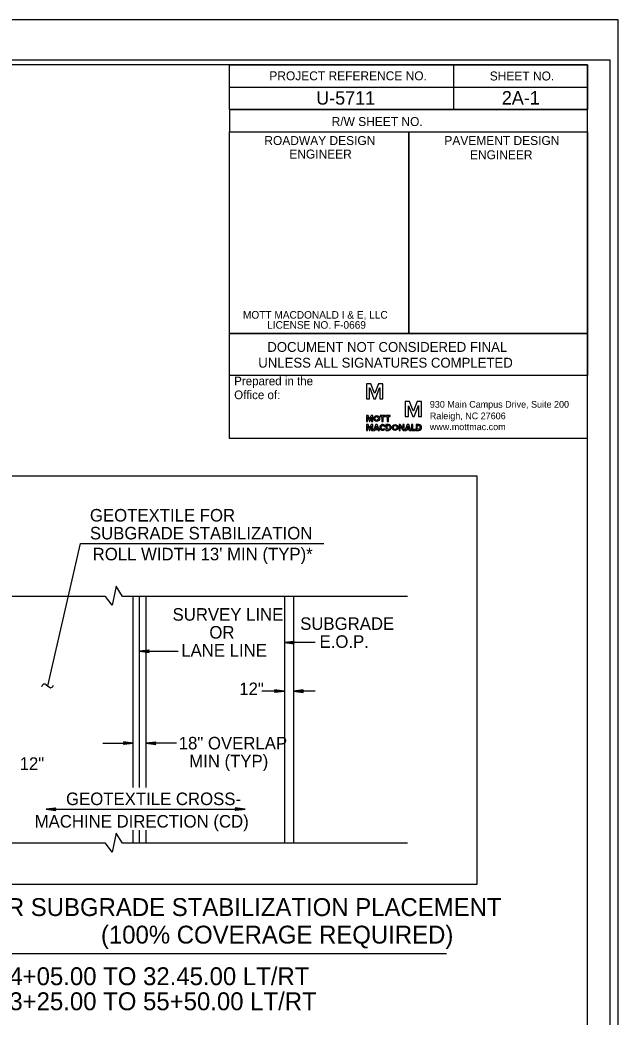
# Model space of a CAD drawing. Extents: x 1901718 to 1902220, y 193828 to 194187.
# Drawn here: x 1902100.8 to 1902134.2, y 194102.3 to 194158 of the extents above; entities that cross this region are included whole.
import ezdxf

# ---------------------------------------------------------------- set-up
doc = ezdxf.new("R2010")
doc.units = 0
for name, color, linetype in [('Old_Level_11', 7, 'Continuous'), ('Old_Level_2', 7, 'Continuous'), ('Old_Level_42', 7, 'Continuous'), ('Old_Level_45', 7, 'Continuous'), ('Prop Dimension Text', 7, 'Continuous'), ('Prop Lane Arrow CELL', 7, 'Continuous'), ('Sheet Border Standard 30in CELL', 7, 'Continuous'), ('Sheet Cutting Line CELL', 7, 'Continuous'), ('Sheet Data Field CELL', 7, 'Continuous'), ('Sheet Plot Border Inside CELL', 7, 'Continuous'), ('Sheet Plot Border Outside CELL', 7, 'Continuous'), ('Sheet Sticker Exception Certification CELL', 7, 'Continuous')]:
    doc.layers.add(name, color=color, linetype=linetype)

msp = doc.modelspace()

# ---------------------------------------------------------------- linework, layer by layer
at = {"layer": 'Old_Level_11'}
msp.add_lwpolyline([(1902088.471, 194132.556), (1902126.343, 194132.556), (1902126.343, 194109.733), (1902088.471, 194109.733)], close=True, dxfattribs=at)
at = {"layer": 'Old_Level_2'}
for p, q in [((1902120.437, 194137.699), (1902120.185, 194137.699)), ((1902120.185, 194137.699), (1902120.185, 194136.849)), ((1902120.642, 194137.174), (1902120.437, 194137.699)), ((1902120.853, 194137.699), (1902120.647, 194137.174)), ((1902121.105, 194137.699), (1902120.853, 194137.699)), ((1902121.105, 194136.849), (1902121.105, 194137.699)), ((1902120.364, 194136.849), (1902120.364, 194137.46)), ((1902120.364, 194137.46), (1902120.366, 194137.46)), ((1902120.366, 194137.46), (1902120.606, 194136.849)), ((1902120.642, 194137.166), (1902120.642, 194137.174)), ((1902120.647, 194137.166), (1902120.642, 194137.166)), ((1902120.647, 194137.174), (1902120.647, 194137.166)), ((1902120.684, 194136.849), (1902120.923, 194137.463)), ((1902120.923, 194137.463), (1902120.925, 194137.463)), ((1902120.925, 194137.463), (1902120.925, 194136.849)), ((1902120.185, 194136.849), (1902120.364, 194136.849)), ((1902120.606, 194136.849), (1902120.684, 194136.849)), ((1902120.925, 194136.849), (1902121.105, 194136.849)), ((1902122.598, 194136.709), (1902122.346, 194136.709)), ((1902122.346, 194136.709), (1902122.346, 194135.859)), ((1902122.803, 194136.184), (1902122.598, 194136.709)), ((1902123.014, 194136.709), (1902122.809, 194136.184)), ((1902123.266, 194136.709), (1902123.014, 194136.709)), ((1902123.266, 194135.859), (1902123.266, 194136.709)), ((1902122.525, 194135.859), (1902122.525, 194136.47)), ((1902122.525, 194136.47), (1902122.528, 194136.47)), ((1902122.528, 194136.47), (1902122.767, 194135.859)), ((1902122.803, 194136.176), (1902122.803, 194136.184)), ((1902122.809, 194136.176), (1902122.803, 194136.176)), ((1902122.809, 194136.184), (1902122.809, 194136.176)), ((1902122.845, 194135.859), (1902123.084, 194136.472)), ((1902123.084, 194136.472), (1902123.087, 194136.472)), ((1902123.087, 194136.472), (1902123.087, 194135.859)), ((1902120.281, 194135.919), (1902120.185, 194135.919)), ((1902120.185, 194135.919), (1902120.185, 194135.594)), ((1902120.185, 194135.594), (1902120.252, 194135.594)), ((1902120.252, 194135.594), (1902120.252, 194135.828)), ((1902120.252, 194135.828), (1902120.255, 194135.828)), ((1902120.252, 194135.828), (1902120.255, 194135.828)), ((1902120.255, 194135.828), (1902120.346, 194135.594)), ((1902120.361, 194135.716), (1902120.281, 194135.919)), ((1902120.346, 194135.594), (1902120.377, 194135.594)), ((1902120.442, 194135.919), (1902120.361, 194135.716)), ((1902120.377, 194135.594), (1902120.468, 194135.828)), ((1902120.538, 194135.919), (1902120.442, 194135.919)), ((1902120.468, 194135.828), (1902120.47, 194135.828)), ((1902120.468, 194135.828), (1902120.47, 194135.828)), ((1902120.468, 194135.828), (1902120.47, 194135.828)), ((1902120.47, 194135.828), (1902120.471, 194135.594)), ((1902120.471, 194135.594), (1902120.538, 194135.594)), ((1902120.538, 194135.594), (1902120.538, 194135.919)), ((1902120.538, 194135.594), (1902120.538, 194135.919)), ((1902122.346, 194135.859), (1902122.525, 194135.859)), ((1902122.767, 194135.859), (1902122.845, 194135.859)), ((1902123.087, 194135.859), (1902123.266, 194135.859)), ((1902120.281, 194135.414), (1902120.185, 194135.414)), ((1902120.185, 194135.414), (1902120.185, 194135.089)), ((1902120.185, 194135.089), (1902120.252, 194135.089)), ((1902120.252, 194135.089), (1902120.252, 194135.323)), ((1902120.252, 194135.323), (1902120.255, 194135.323)), ((1902120.255, 194135.323), (1902120.346, 194135.089)), ((1902120.361, 194135.211), (1902120.281, 194135.414)), ((1902120.346, 194135.089), (1902120.377, 194135.089)), ((1902120.442, 194135.414), (1902120.361, 194135.211)), ((1902120.377, 194135.089), (1902120.468, 194135.323)), ((1902120.538, 194135.414), (1902120.442, 194135.414)), ((1902120.468, 194135.323), (1902120.47, 194135.323)), ((1902120.47, 194135.323), (1902120.471, 194135.089)), ((1902120.471, 194135.089), (1902120.538, 194135.089)), ((1902120.538, 194135.089), (1902120.538, 194135.414)), ((1902121.221, 194135.156), (1902121.164, 194135.184)), ((1902121.221, 194135.156), (1902121.164, 194135.184)), ((1902121.172, 194135.308), (1902121.229, 194135.335)), ((1902121.172, 194135.308), (1902121.229, 194135.334)), ((1902121.422, 194135.414), (1902121.274, 194135.414)), ((1902121.274, 194135.414), (1902121.274, 194135.246)), ((1902121.274, 194135.246), (1902121.274, 194135.089)), ((1902121.274, 194135.089), (1902121.422, 194135.089)), ((1902121.341, 194135.152), (1902121.341, 194135.354)), ((1902121.341, 194135.354), (1902121.422, 194135.354)), ((1902121.422, 194135.152), (1902121.341, 194135.152)), ((1902122.955, 194135.414), (1902122.955, 194135.414)), ((1902123.104, 194135.414), (1902122.955, 194135.414)), ((1902122.955, 194135.414), (1902122.955, 194135.246)), ((1902122.955, 194135.246), (1902122.955, 194135.089)), ((1902122.955, 194135.089), (1902123.104, 194135.089)), ((1902123.023, 194135.152), (1902123.023, 194135.354)), ((1902123.023, 194135.354), (1902123.104, 194135.354)), ((1902123.104, 194135.152), (1902123.023, 194135.152)), ((1902123.104, 194135.352), (1902123.104, 194135.352))]:
    msp.add_line(p, q, dxfattribs=at)
for points in [[(1902120.946, 194135.859), (1902121.04, 194135.859), (1902121.04, 194135.594), (1902121.11, 194135.594), (1902121.11, 194135.859), (1902121.204, 194135.859), (1902121.204, 194135.919), (1902120.946, 194135.919), (1902120.946, 194135.859)], [(1902121.245, 194135.859), (1902121.339, 194135.859), (1902121.339, 194135.594), (1902121.409, 194135.594), (1902121.409, 194135.859), (1902121.502, 194135.859), (1902121.502, 194135.919), (1902121.245, 194135.919), (1902121.245, 194135.859)], [(1902120.577, 194135.089), (1902120.655, 194135.089), (1902120.676, 194135.144), (1902120.816, 194135.144), (1902120.837, 194135.089), (1902120.912, 194135.089), (1902120.788, 194135.414), (1902120.702, 194135.414), (1902120.577, 194135.089)], [(1902120.694, 194135.204), (1902120.746, 194135.344), (1902120.798, 194135.204), (1902120.694, 194135.204)], [(1902122.069, 194135.3), (1902122.072, 194135.3), (1902122.228, 194135.089), (1902122.293, 194135.089), (1902122.293, 194135.414), (1902122.225, 194135.414), (1902122.225, 194135.209), (1902122.072, 194135.414), (1902122.004, 194135.414), (1902122.004, 194135.089), (1902122.069, 194135.089), (1902122.069, 194135.3)], [(1902122.334, 194135.089), (1902122.412, 194135.089), (1902122.433, 194135.144), (1902122.573, 194135.144), (1902122.594, 194135.089), (1902122.67, 194135.089), (1902122.545, 194135.414), (1902122.459, 194135.414), (1902122.334, 194135.089)], [(1902122.451, 194135.204), (1902122.503, 194135.344), (1902122.555, 194135.204), (1902122.451, 194135.204)], [(1902122.917, 194135.089), (1902122.917, 194135.147), (1902122.776, 194135.147), (1902122.776, 194135.414), (1902122.709, 194135.414), (1902122.709, 194135.089), (1902122.917, 194135.089)], [(1902122.917, 194135.089), (1902122.917, 194135.147), (1902122.776, 194135.147), (1902122.776, 194135.414), (1902122.709, 194135.414), (1902122.709, 194135.089), (1902122.917, 194135.09), (1902122.917, 194135.147)]]:
    msp.add_lwpolyline(points, dxfattribs=at)
msp.add_arc((1902123.104, 194135.252), 0.162, 270, 90, dxfattribs=at)
for centre, major_axis, ratio in [((1902120.759, 194135.756), (0, 0.162), 0.993118), ((1902120.759, 194135.756), (0, 0.106), 0.916103), ((1902121.786, 194135.252), (0, 0.162), 0.993118), ((1902121.786, 194135.252), (0, 0.106), 0.916103)]:
    msp.add_ellipse(centre, major_axis=major_axis, ratio=ratio, dxfattribs=at)
for centre, major_axis, ratio, start_param, end_param in [((1902121.09, 194135.252), (0, 0.162), 0.993118, 5.246647, 10.366427), ((1902121.09, 194135.252), (0, 0.162), 0.993118, 5.246647, 10.366427), ((1902121.09, 194135.252), (0, 0.106), 0.916103, 5.276876, 9.424778), ((1902121.09, 194135.252), (0, 0.106), 0.916103, 5.276876, 10.296021), ((1902121.09, 194135.252), (0, 0.106), 0.916103, 3.141593, 4.012835), ((1902121.422, 194135.252), (0, -0.162), 0.930276, 0, 3.141593), ((1902121.422, 194135.253), (0, -0.101), 0.900832, 0, 3.141593), ((1902123.104, 194135.253), (0, -0.101), 0.900832, 0, 3.141593)]:
    msp.add_ellipse(centre, major_axis=major_axis, ratio=ratio, start_param=start_param, end_param=end_param, dxfattribs=at)
at = {"layer": 'Old_Level_42'}
msp.add_lwpolyline([(1902132.544, 194134.629), (1902112.539, 194134.629), (1902112.539, 194138.159)], dxfattribs=at)
at = {"layer": 'Prop Dimension Text'}
for p, q in [((1902102.377, 194120.813), (1902104.208, 194128.773)), ((1902104.208, 194128.773), (1902117.81, 194128.773)), ((1902107.147, 194115.152), (1902107.147, 194125.82)), ((1902107.507, 194115.152), (1902107.507, 194125.82)), ((1902107.867, 194115.152), (1902107.867, 194125.82)), ((1902115.597, 194125.82), (1902115.597, 194112.026)), ((1902116.112, 194125.82), (1902116.112, 194112.026)), ((1902115.597, 194123.24), (1902116.142, 194123.314)), ((1902116.132, 194123.304), (1902115.597, 194123.24)), ((1902115.597, 194123.24), (1902116.122, 194123.293)), ((1902116.112, 194123.283), (1902115.597, 194123.24)), ((1902115.597, 194123.24), (1902116.101, 194123.271)), ((1902116.092, 194123.262), (1902115.597, 194123.24)), ((1902115.597, 194123.24), (1902116.082, 194123.251)), ((1902117.311, 194123.24), (1902115.597, 194123.24)), ((1902115.597, 194123.24), (1902116.142, 194123.167)), ((1902116.072, 194123.24), (1902115.597, 194123.24)), ((1902116.082, 194123.23), (1902115.597, 194123.24)), ((1902115.597, 194123.24), (1902116.092, 194123.22)), ((1902116.101, 194123.209), (1902115.597, 194123.24)), ((1902115.597, 194123.24), (1902116.112, 194123.198)), ((1902116.122, 194123.187), (1902115.597, 194123.24)), ((1902115.597, 194123.24), (1902116.132, 194123.178)), ((1902116.142, 194123.314), (1902116.072, 194123.24)), ((1902116.072, 194123.24), (1902116.142, 194123.167)), ((1902107.507, 194122.767), (1902108.052, 194122.84)), ((1902107.507, 194122.767), (1902108.042, 194122.83)), ((1902108.032, 194122.82), (1902107.507, 194122.767)), ((1902107.507, 194122.767), (1902108.022, 194122.81)), ((1902108.011, 194122.798), (1902107.507, 194122.767)), ((1902107.507, 194122.767), (1902108.002, 194122.788)), ((1902107.991, 194122.777), (1902107.507, 194122.767)), ((1902107.507, 194122.767), (1902108.052, 194122.693)), ((1902108.042, 194122.704), (1902107.507, 194122.767)), ((1902107.507, 194122.767), (1902108.032, 194122.714)), ((1902108.022, 194122.725), (1902107.507, 194122.767)), ((1902107.507, 194122.767), (1902108.011, 194122.736)), ((1902108.002, 194122.746), (1902107.507, 194122.767)), ((1902107.507, 194122.767), (1902107.991, 194122.756)), ((1902107.982, 194122.767), (1902107.507, 194122.767)), ((1902107.507, 194122.767), (1902109.672, 194122.767)), ((1902107.982, 194122.767), (1902108.052, 194122.84)), ((1902108.052, 194122.693), (1902107.982, 194122.767)), ((1902102.045, 194120.781), (1902102.07, 194120.833)), ((1902102.281, 194120.881), (1902102.472, 194120.745)), ((1902102.657, 194120.791), (1902102.693, 194120.86)), ((1902115.597, 194120.526), (1902114.332, 194120.526)), ((1902115.597, 194120.526), (1902115.052, 194120.599)), ((1902115.122, 194120.526), (1902115.052, 194120.599)), ((1902115.597, 194120.526), (1902115.052, 194120.452)), ((1902115.052, 194120.452), (1902115.122, 194120.526)), ((1902115.597, 194120.526), (1902115.062, 194120.589)), ((1902115.062, 194120.463), (1902115.597, 194120.526)), ((1902115.072, 194120.579), (1902115.597, 194120.526)), ((1902115.597, 194120.526), (1902115.072, 194120.473)), ((1902115.597, 194120.526), (1902115.082, 194120.569)), ((1902115.082, 194120.484), (1902115.597, 194120.526)), ((1902115.092, 194120.557), (1902115.597, 194120.526)), ((1902115.597, 194120.526), (1902115.092, 194120.495)), ((1902115.597, 194120.526), (1902115.102, 194120.547)), ((1902115.102, 194120.505), (1902115.597, 194120.526)), ((1902115.112, 194120.536), (1902115.597, 194120.526)), ((1902115.597, 194120.526), (1902115.112, 194120.515)), ((1902115.122, 194120.526), (1902115.597, 194120.526)), ((1902116.112, 194120.526), (1902116.657, 194120.6)), ((1902116.647, 194120.59), (1902116.112, 194120.526)), ((1902116.112, 194120.526), (1902116.636, 194120.579)), ((1902116.627, 194120.569), (1902116.112, 194120.526)), ((1902116.112, 194120.526), (1902116.616, 194120.558)), ((1902116.607, 194120.548), (1902116.112, 194120.526)), ((1902116.112, 194120.526), (1902116.596, 194120.537)), ((1902117.311, 194120.526), (1902116.112, 194120.526)), ((1902116.112, 194120.526), (1902116.657, 194120.453)), ((1902116.587, 194120.526), (1902116.112, 194120.526)), ((1902116.596, 194120.516), (1902116.112, 194120.526)), ((1902116.112, 194120.526), (1902116.607, 194120.506)), ((1902116.616, 194120.495), (1902116.112, 194120.526)), ((1902116.112, 194120.526), (1902116.627, 194120.484)), ((1902116.636, 194120.473), (1902116.112, 194120.526)), ((1902116.112, 194120.526), (1902116.647, 194120.464)), ((1902116.657, 194120.6), (1902116.587, 194120.526)), ((1902116.587, 194120.526), (1902116.657, 194120.453)), ((1902105.446, 194117.625), (1902107.147, 194117.625)), ((1902107.147, 194117.625), (1902106.602, 194117.699)), ((1902106.602, 194117.699), (1902106.672, 194117.625)), ((1902107.147, 194117.625), (1902106.602, 194117.552)), ((1902106.672, 194117.625), (1902106.602, 194117.552)), ((1902106.611, 194117.688), (1902107.147, 194117.625)), ((1902107.147, 194117.625), (1902106.611, 194117.562)), ((1902107.147, 194117.625), (1902106.622, 194117.678)), ((1902106.622, 194117.572), (1902107.147, 194117.625)), ((1902106.632, 194117.667), (1902107.147, 194117.625)), ((1902107.147, 194117.625), (1902106.632, 194117.582)), ((1902107.147, 194117.625), (1902106.642, 194117.656)), ((1902106.642, 194117.594), (1902107.147, 194117.625)), ((1902106.652, 194117.646), (1902107.147, 194117.625)), ((1902107.147, 194117.625), (1902106.652, 194117.604)), ((1902107.147, 194117.625), (1902106.662, 194117.636)), ((1902106.662, 194117.615), (1902107.147, 194117.625)), ((1902106.672, 194117.625), (1902107.147, 194117.625)), ((1902107.867, 194117.625), (1902108.412, 194117.698)), ((1902107.867, 194117.625), (1902108.402, 194117.687)), ((1902108.392, 194117.678), (1902107.867, 194117.625)), ((1902107.867, 194117.625), (1902108.382, 194117.667)), ((1902108.371, 194117.656), (1902107.867, 194117.625)), ((1902107.867, 194117.625), (1902108.362, 194117.645)), ((1902108.351, 194117.635), (1902107.867, 194117.625)), ((1902107.867, 194117.625), (1902108.412, 194117.551)), ((1902108.402, 194117.561), (1902107.867, 194117.625)), ((1902107.867, 194117.625), (1902108.392, 194117.572)), ((1902108.382, 194117.582), (1902107.867, 194117.625)), ((1902107.867, 194117.625), (1902108.371, 194117.593)), ((1902108.362, 194117.603), (1902107.867, 194117.625)), ((1902107.867, 194117.625), (1902108.351, 194117.614)), ((1902108.342, 194117.625), (1902107.867, 194117.625)), ((1902109.568, 194117.625), (1902107.867, 194117.625)), ((1902108.342, 194117.625), (1902108.412, 194117.698)), ((1902108.412, 194117.551), (1902108.342, 194117.625)), ((1902102.283, 194113.931), (1902102.828, 194114.005)), ((1902102.283, 194113.931), (1902102.818, 194113.994)), ((1902102.808, 194113.984), (1902102.283, 194113.931)), ((1902102.283, 194113.931), (1902102.798, 194113.974)), ((1902102.787, 194113.963), (1902102.283, 194113.931)), ((1902102.283, 194113.931), (1902102.778, 194113.952)), ((1902102.768, 194113.942), (1902102.283, 194113.931)), ((1902102.283, 194113.931), (1902102.828, 194113.858)), ((1902102.818, 194113.868), (1902102.283, 194113.931)), ((1902102.283, 194113.931), (1902102.808, 194113.879)), ((1902102.798, 194113.889), (1902102.283, 194113.931)), ((1902102.283, 194113.931), (1902102.787, 194113.9)), ((1902102.778, 194113.91), (1902102.283, 194113.931)), ((1902102.283, 194113.931), (1902102.768, 194113.921)), ((1902102.758, 194113.931), (1902102.283, 194113.931)), ((1902102.283, 194113.931), (1902113.403, 194113.931)), ((1902102.758, 194113.931), (1902102.828, 194114.005)), ((1902102.828, 194113.858), (1902102.758, 194113.931)), ((1902113.403, 194113.931), (1902112.858, 194114.005)), ((1902112.858, 194114.005), (1902112.928, 194113.931)), ((1902113.403, 194113.931), (1902112.858, 194113.858)), ((1902112.928, 194113.931), (1902112.858, 194113.858)), ((1902112.868, 194113.994), (1902113.403, 194113.931)), ((1902113.403, 194113.931), (1902112.868, 194113.868)), ((1902113.403, 194113.931), (1902112.878, 194113.984)), ((1902112.878, 194113.878), (1902113.403, 194113.931)), ((1902112.888, 194113.973), (1902113.403, 194113.931)), ((1902113.403, 194113.931), (1902112.888, 194113.888)), ((1902113.403, 194113.931), (1902112.899, 194113.962)), ((1902112.899, 194113.9), (1902113.403, 194113.931)), ((1902112.908, 194113.952), (1902113.403, 194113.931)), ((1902113.403, 194113.931), (1902112.908, 194113.91)), ((1902113.403, 194113.931), (1902112.919, 194113.942)), ((1902112.919, 194113.921), (1902113.403, 194113.931)), ((1902112.928, 194113.931), (1902113.403, 194113.931)), ((1902107.147, 194112.026), (1902107.147, 194112.759)), ((1902107.507, 194112.026), (1902107.507, 194112.759)), ((1902107.867, 194112.026), (1902107.867, 194112.759)), ((1902090.826, 194105.871), (1902124.653, 194105.871))]:
    msp.add_line(p, q, dxfattribs=at)
for points in [[(1902122.486, 194125.82), (1902106.554, 194125.82), (1902106.197, 194126.385), (1902105.971, 194125.332), (1902105.603, 194125.82), (1902091.057, 194125.82)], [(1902122.486, 194112.026), (1902106.554, 194112.026), (1902106.197, 194112.591), (1902105.971, 194111.538), (1902105.603, 194112.026), (1902091.057, 194112.026)]]:
    msp.add_lwpolyline(points, dxfattribs=at)
for centre, radius, start, end in [((1902102.193, 194120.783), 0.132, 48.0321, 157.831), ((1902102.547, 194120.834), 0.117, 230.477, 338.7625)]:
    msp.add_arc(centre, radius, start, end, dxfattribs=at)
at = {"layer": 'Sheet Border Standard 30in CELL'}
for p, q in [((1902125.044, 194155.509), (1902125.044, 194153.009)), ((1902112.539, 194154.259), (1902132.544, 194154.259)), ((1902112.539, 194153.009), (1902132.544, 194153.009)), ((1902112.539, 194153.009), (1902112.539, 194151.759)), ((1902112.539, 194153.009), (1902132.544, 194153.009)), ((1902122.544, 194151.759), (1902122.544, 194140.514))]:
    msp.add_line(p, q, dxfattribs=at)
for points in [[(1902132.544, 194155.514), (1901982.544, 194155.514), (1901982.544, 194050.514), (1902132.544, 194050.514)], [(1902112.539, 194155.514), (1902132.544, 194155.514), (1902132.544, 194153.009), (1902112.539, 194153.009)], [(1902112.539, 194151.759), (1902122.544, 194151.759), (1902122.544, 194140.509), (1902112.539, 194140.509)], [(1902122.544, 194151.759), (1902132.544, 194151.759), (1902132.544, 194140.509), (1902122.544, 194140.509)]]:
    msp.add_lwpolyline(points, close=True, dxfattribs=at)
at = {"layer": 'Sheet Cutting Line CELL'}
msp.add_line((1902134.244, 194158.014), (1901965.844, 194158.014), dxfattribs=at)
at = {"layer": 'Sheet Plot Border Inside CELL'}
msp.add_lwpolyline([(1902133.794, 194155.769), (1901967.144, 194155.769), (1901967.144, 194050.259), (1902133.794, 194050.259)], close=True, dxfattribs=at)
at = {"layer": 'Sheet Plot Border Outside CELL'}
msp.add_lwpolyline([(1902134.244, 194158.014), (1901965.844, 194158.014), (1901965.844, 194048.014), (1902134.244, 194048.014)], close=True, dxfattribs=at)
at = {"layer": 'Sheet Sticker Exception Certification CELL'}
for p, q in [((1902112.539, 194138.159), (1902112.539, 194140.509)), ((1902112.539, 194140.509), (1902132.542, 194140.509)), ((1902132.542, 194140.508), (1902132.542, 194138.158)), ((1902132.542, 194138.159), (1902112.539, 194138.159))]:
    msp.add_line(p, q, dxfattribs=at)

# ---------------------------------------------------------------- texts
at = {"layer": 'Old_Level_2'}
for s, height, p in [('Prepared in the ', 0.48186, (1902112.794, 194137.609)), ('Office of:', 0.4819, (1902112.794, 194136.834))]:
    msp.add_text(s, height=height, dxfattribs=at).set_placement(p)
for s, p in [('930 Main Campus Drive, Suite 200', (1902123.726, 194136.357)), ('Raleigh, NC 27606', (1902123.726, 194135.712)), ('www.mottmac.com', (1902123.726, 194135.103))]:
    msp.add_text(s, height=0.375, rotation=360, dxfattribs=at).set_placement(p)
at = {"layer": 'Old_Level_45'}
for s, p in [('MOTT MACDONALD I & E, LLC', (1902113.285, 194141.332)), (' LICENSE NO. F-0669', (1902114.481, 194140.769))]:
    msp.add_text(s, height=0.42187, rotation=360, dxfattribs=at).set_placement(p)
at = {"layer": 'Prop Dimension Text'}
for s, p in [('GEOTEXTILE FOR', (1902104.733, 194130)), ('SUBGRADE STABILIZATION', (1902104.733, 194129)), ("ROLL WIDTH 13' MIN (TYP)*", (1902104.885, 194127.832)), ('SURVEY LINE', (1902109.35, 194124.461)), ('SUBGRADE', (1902116.482, 194123.947)), ('OR', (1902111.407, 194123.461)), ('E.O.P.', (1902117.564, 194122.944)), ('LANE LINE', (1902109.836, 194122.456)), ('12"', (1902113.078, 194120.304)), ('18" OVERLAP', (1902109.695, 194117.272)), ('12"', (1902100.808, 194116.129)), ('MIN (TYP)', (1902110.28, 194116.269)), ('GEOTEXTILE CROSS-', (1902103.399, 194114.161))]:
    msp.add_text(s, height=0.7, dxfattribs=at).set_placement(p)
for s, height, p in [('MACHINE DIRECTION (CD)', 0.7, (1902101.646, 194112.905)), ('GEOTEXTILE FOR SUBGRADE STABILIZATION PLACEMENT', 0.99999, (1902089.465, 194107.965)), ('(100% COVERAGE REQUIRED)', 0.99999, (1902105.349, 194106.426))]:
    msp.add_text(s, height=height, rotation=360, dxfattribs=at).set_placement(p)
at = {"layer": 'Prop Lane Arrow CELL'}
for s, p in [('-L- STA. 14+05.00 TO 32.45.00 LT/RT', (1902094.138, 194104.104)), ('-L- STA. 33+25.00 TO 55+50.00 LT/RT', (1902094.138, 194102.704))]:
    msp.add_text(s, height=0.99999, dxfattribs=at).set_placement(p)
at = {"layer": 'Sheet Border Standard 30in CELL'}
for s, height, p in [('PROJECT REFERENCE NO.', 0.50001, (1902114.759, 194154.644)), ('SHEET NO.', 0.5, (1902127.074, 194154.634)), ('R/W SHEET NO.', 0.50001, (1902118.239, 194152.089)), ('ROADWAY DESIGN', 0.50001, (1902114.479, 194151.029)), ('PAVEMENT DESIGN', 0.50001, (1902124.538, 194151.029)), ('ENGINEER', 0.5, (1902115.874, 194150.274)), ('ENGINEER', 0.5, (1902125.969, 194150.234))]:
    msp.add_text(s, height=height, dxfattribs=at).set_placement(p)
at = {"layer": 'Sheet Data Field CELL'}
for s, p in [('U-5711', (1902117.377, 194153.284)), ('2A-1', (1902127.749, 194153.289))]:
    msp.add_text(s, height=0.75, dxfattribs=at).set_placement(p)
at = {"layer": 'Sheet Sticker Exception Certification CELL'}
for s, p in [('DOCUMENT NOT CONSIDERED FINAL', (1902114.646, 194139.475)), ('UNLESS ALL SIGNATURES COMPLETED', (1902114.139, 194138.595))]:
    msp.add_text(s, height=0.55, dxfattribs=at).set_placement(p)

doc.saveas('drawing.dxf')
